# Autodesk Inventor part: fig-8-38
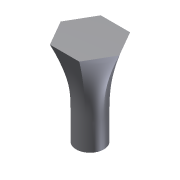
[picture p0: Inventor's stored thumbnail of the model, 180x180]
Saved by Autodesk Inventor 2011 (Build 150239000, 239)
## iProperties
Created: 2004-05
Part Number: fig-8-38
Document SubType Name: Modeling
Designer: CADCIM Technologies
Manufacturer: Standard
Standards Organization: Custom
Density: 1 g/cm^3
Author: CADCIM Technologies
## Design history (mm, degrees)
sketch "Sketch1"
  geometry: C1 r 16.344 at (0, 0)
  constraints: 1 centre point
extrude "Extrusion1" new body sketch "Sketch1" distance "d0" = 30.75; taper "d1" = 0 deg
workplane "Work Plane1"
sketch "Sketch2"
  geometry: L1 (34.788, 0)-(17.394, -30.128); L2 (17.394, -30.128)-(-17.394, -30.128); L3 (-17.394, -30.128)-(-34.788, 0); L4 (-34.788, 0)-(-17.394, 30.128); L5 (-17.394, 30.128)-(17.394, 30.128); L6 (17.394, 30.128)-(34.788, 0); 2 further points
  constraints: 12 end point, 1 coincident, 12 other
loft "Loft2" sketch "Sketch2" dims "d8" = 90 deg, "d11" = 10, "d12" = 0, "d13" = 90 deg
  node "Edges2"
body "Solid1"
other parameters: "d2" = 75
